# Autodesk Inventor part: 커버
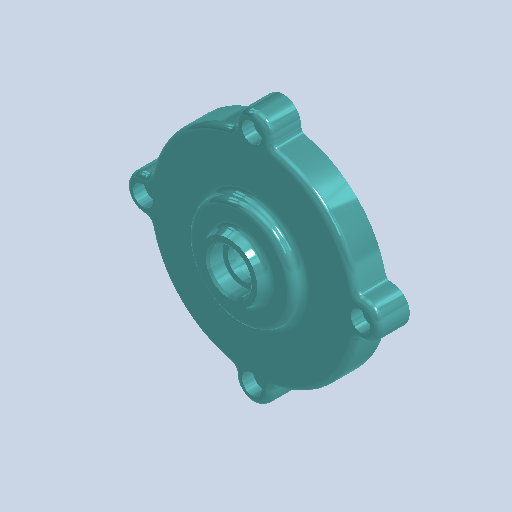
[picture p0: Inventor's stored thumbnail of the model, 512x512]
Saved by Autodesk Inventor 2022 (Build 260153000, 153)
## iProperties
Created: 2021-07
Part Number: 커버
Document SubType Name: 모델링
Designer: mdu
Material: 알루미늄 6061
Density: 2.71 g/cm^3
Mass: 196.659 g
Surface Area: 278.607 cm^2
Volume: 72.5678 cm^3
Appearance: 커버
변환 표준: STEP AP214IS
파일 이름: C:\Users\SeoGD\Desktop\?쒗뿕\而ㅻ쾭-1.stp
전처리기: Build: 253, Release: 2010 SP1 - Date: Wed 07/29/2009
전송 단위: 밀리미터
불확실성: 0.01
Author: mdu
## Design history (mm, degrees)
sketch "스케치1"
  geometry: L1 (0, 0)-(0, 26); L2 (50, 0)-(50, 15); L3 (50, 15)-(25, 15); L4 (25, 15)-(25, 21); L5 (25, 21)-(15, 21); L6 (15, 21)-(13.66, 26); L7 (13.66, 26)-(10, 26); L8 (50, 0)-(45, 0); L9 (45, 0)-(45, 10); L10 (45, 10)-(14.5, 10); L11 (14.5, 10)-(13.266, 3); L12 (13.266, 3)-(11, 3); L13 (11, 3)-(11, 16); L14 (11, 16)-(7.5, 16); L15 (7.5, 16)-(7.5, 19); L16 (7.5, 19)-(10, 19); L17 (10, 19)-(10, 26)
  constraints: 34 end point, 10 parallel, 2 perpendicular, 2 point on line, 1 vertical
  dimensions: "d11" = 100 diameter of L2 L1; "d12" = 22 diameter of L13 L1; "d13" = 90 diameter of L9 L1; "d14" = 15 distance between parallel lines of L3 L8; "d15" = 10 distance between parallel lines of L8 L10; "d16" = 29 diameter of L10.end L1; "d17" = 100 deg angle of L11 L10; "d18" = 7 distance between parallel lines of L12 L10; "d19" = 13 distance between parallel lines of L14 L12; "d20" = 3 distance between parallel lines of L16 L14; "d21" = 15 diameter of L15 L1; "d22" = 20 diameter of L17 L1; "d23" = 30 diameter of L5.end L1; "d24" = 6 distance between parallel lines of L5 L3; "d25" = 50 diameter of L4 L1; "d26" = 105 deg angle of L5 L6; "d50" = 26 distance of L1.start L1.end
revolve "회전1" sketch "스케치1" stored, may be unused: angle "d27" = 90 deg
sketch "스케치2" dims "d29" = 104
  geometry: A1 r 8.5 centre (0, 52) between (8.074, 49.344) and (-8.074, 49.344); A2 r 50 centre (0, 0) between (-8.074, 49.344) and (8.074, 49.344) reference; 2 further points
  constraints: 4 point on circle, 2 vertical alignment, 1 centre point, 1 coincident, 2 other
  dimensions: "d28" = 17 diameter of A1
extrude "돌출1" join sketch "스케치2" stored distance "d30" = 10; taper "d31" = 0 deg
fillet "모깎기3" dims "d32" = 3
fillet "모깎기4" dims "d45" = 3, "d46" = 0.2
chamfer "모따기1" distance "d47" = 1; stored, may be unused: second distance "d48" = 2, angle "d49" = 45 deg
hole "구멍2" diameter "d38" = 5.5; stored, may be unused: countersink angle "d42" = 90 deg, drill point angle "d44" = 118 deg; dims "d36" = 10, "d37" = 10, "d39" = 6, "d40" = 9.5, "d41" = 5.4, "d43" = 8
node "솔리드1"
node "솔리드 본체"
node "곡면 본체"
pattern_circular "원형 패턴1" dims angle "d34" = 360 deg
pattern_circular "원형 패턴2" dims angle "d52" = 360 deg
node "솔리드2"
